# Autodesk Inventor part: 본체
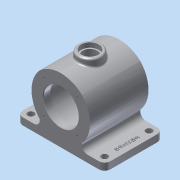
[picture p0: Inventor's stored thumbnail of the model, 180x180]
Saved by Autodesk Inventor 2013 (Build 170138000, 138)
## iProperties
Company: 한국ATC센터
Created: 2014-08
Part Number: 본체
Document SubType Name: Modeling
Designer: KYOUNG IL JANG
Density: 2.71 g/cm^3
Material: 알루미늄 6061
Mass: 1595.16 g
Surface Area: 933.382 cm^2
Volume: 588.618 cm^3
Author: KYOUNG IL JANG
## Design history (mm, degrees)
sketch "스케치1"
  geometry: L1 (-50, 0)-(50, 0); L2 (-36.062, 36.062)-(36.062, 36.062); L3 (36.062, 36.062)-(36.062, -36.062); L4 (36.062, -36.062)-(-36.062, -36.062); L5 (-36.062, -36.062)-(-36.062, 36.062); A1 r 53.623 centre (-3.623, 0) between (36.062, -36.062) and (36.062, 36.062); A2 r 53.623 centre (3.623, 0) between (-36.062, 36.062) and (-36.062, -36.062); A3 r 53.623 centre (0, -3.623) between (36.062, 36.062) and (-36.062, 36.062); A4 r 53.623 centre (0, 3.623) between (-36.062, -36.062) and (36.062, -36.062); 4 further points
  constraints: 11 point on circle, 10 end point, 5 coincident, 4 centre point, 4 horizontal alignment, 3 equal radius, 2 horizontal, 2 parallel, 2 perpendicular, 1 midpoint
  dimensions: "d83" = 51 distance of L2.end point (0, 0); "d84" = 100 distance of L1.end L1.start
extrude "돌출1" new body sketch "스케치1" stored distance "d9" = 100; taper "d10" = 0 deg
node "작업 평면1"
sketch "스케치2"
  geometry: L1 (75, 50)-(-75, 50); L2 (-75, 50)-(-75, -50); L3 (-75, -50)-(75, -50); L4 (75, -50)-(75, 50); 4 further points
  constraints: 8 end point, 3 midpoint, 2 parallel, 2 vertical alignment, 1 horizontal, 1 horizontal alignment, 1 perpendicular
  dimensions: "d14" = 150 distance of L2.end L3.end; "d82" = 100 distance of L1.end L2.end
extrude "돌출2" join sketch "스케치2" distance "d15" = 12; taper "d16" = 0 deg
node "작업 평면3"
  node "작업 평면4"
sketch "스케치3"
  geometry: C1 r 20 at (0, 0); 1 further point
  constraints: 2 coincident, 1 centre point
  dimensions: "d19" = 40 diameter of C1
extrude "돌출3" join sketch "스케치3" stored distance "d23" = 12; taper "d24" = 0 deg
node "작업 평면6"
  node "작업 평면5"
sketch "스케치4"
  geometry: C1 r 37.5 at (0, 0); 1 further point
  constraints: 1 centre point, 1 coincident
  dimensions: "d25" = 75 diameter of C1
extrude "돌출4" cut sketch "스케치4" stored distance "d26" = 76; taper "d27" = 0 deg
sketch "스케치5"
  geometry: C1 r 30 at (0, 0); 1 further point
  constraints: 1 centre point, 1 coincident
  dimensions: "d28" = 60 diameter of C1
extrude "돌출5" cut sketch "스케치5" stored distance "d29" = 116; taper "d30" = 0 deg
hole "구멍1" diameter "d33" = 25; stored, may be unused: countersink angle "d37" = 90 deg, drill point angle "d39" = 0 deg; dims "d31" = 10, "d32" = 10, "d34" = 6, "d35" = 30, "d36" = 8, "d38" = 40
sketch "스케치6"
  geometry: L1 (-75, -50)-(-75, 50) reference; L2 (-75, 50)-(75, 50) reference; L3 (75, -50)-(-75, -50) reference; L4 (75, 50)-(75, -50) reference; L5 (0, -50)-(0, 50); L6 (-75, 0)-(75, 0); L7 (-63, -38)-(63, 38); C1 r 5.5 at (-63, -38); C2 r 5.5 at (-63, 38); C3 r 5.5 at (63, -38); C4 r 5.5 at (63, 38); 2 further points
  constraints: 6 end point, 6 midpoint, 4 centre point, 2 equal radius, 2 horizontal alignment, 2 vertical alignment
  dimensions: "d49" = 11 diameter of C1; "d50" = 11 diameter of C2; "d100" = 12 distance from line of L2 C2.centre; "d101" = 12 distance from line of C2.centre L1
extrude "돌출6" cut sketch "스케치6" distance "d53" = 116; taper "d54" = 0 deg
sketch "스케치8"
  geometry: L1 (75, 50)-(75, -50) reference; 2 further points
  constraints: 1 horizontal alignment, 1 other
  dimensions: "d55" = 12 distance from line of L1 point (63, 0)
feature "엠보싱1" sketch "스케치8" dims "d57" = 1, "d58" = 0, "d83" = 51, "d84" = 100
fillet "모깎기2" dims "d60" = 10
fillet "모깎기5" dims "d63" = 10
fillet "모깎기7" dims "d65" = 3
sketch "스케치9"
  geometry: L1 (0, 0)-(-28.284, 28.284); L2 (0, 0)-(0, 40); C1 r 30 at (0, 0) reference; A1 r 40 centre (0, 0) between (-28.284, 28.284) and (0, 40); 1 further point
  constraints: 4 end point, 2 coincident, 2 point on circle, 1 centre point, 1 vertical
  dimensions: "d66" = 80 diameter of A1; "d67" = 45 deg angle of L1 L2
hole "M4" sketch "스케치9" at (-28.284, 28.284) diameter "d68" = 3.242; stored, may be unused: countersink angle "d72" = 90 deg, drill point angle "d74" = 118 deg; dims "d69" = 8, "d70" = 30, "d71" = 8, "d73" = 10
fillet "모깎기8" dims "d78" = 3
chamfer "모따기1" distance "d79" = 1; stored, may be unused: second distance "d80" = 2, angle "d81" = 45 deg
node "솔리드1"
pattern_circular "원형 패턴1" dims angle "d76" = 360 deg
mirror "대칭1"
